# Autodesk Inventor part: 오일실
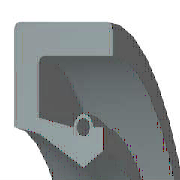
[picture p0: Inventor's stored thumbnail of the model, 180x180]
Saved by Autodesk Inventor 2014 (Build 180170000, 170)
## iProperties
IsCustomPart: 0
Created: 2016-05
Part Number: 오일실
Material: 고무
Description: 오일-실
Document SubType Name: Modeling
Standard: KS B 2804
Designer: mduedu
Standards Organization: KS
Language: ko-KR
Size Designation: S - 17 30 8
Categories: <MemberInstance><Categories><Category DisplayName="샤프트 부품" InternalName="7f7aeb1f-a693-4053-b835-cee3144e0d98" Mnemonic="SHFT"><Category DisplayName="실링" Intern
Density: 0.93 g/cm^3
Appearance: 고무 - 검은색 - 버전 1.1
Author: mduedu
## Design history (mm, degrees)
revolve "본체" stored, may be unused: angle "d17" = 90 deg
revolve "스프링1" stored, may be unused: angle "d18" = 90 deg
body "Solid1"
sketch "스케치1"
  geometry: L1 (0, 15)-(8, 15); L2 (8, 15)-(8, 13.75); L3 (8, 13.75)-(1.75, 13.75); L4 (0, 15)-(0, 10.6); L5 (0, 10.6)-(1.75, 10.25); L6 (1.75, 10.25)-(4.9, 8.5); L7 (4.9, 8.5)-(0, 8.5); L8 (6.3, 9.375)-(6.3, 10.6); L9 (0, 0)-(9.586, 0) reference; L10 (4.9, 8.5)-(6.3, 9.375); L11 (0, 18)-(0, -3) reference; L12 (-1.917, 0)-(11.503, 0) reference; L13 (4.2, 10.6)-(1.75, 11.09); L14 (1.75, 11.09)-(1.75, 13.75); L15 (6.3, 10.6)-(5.6, 10.6); C1 r 0.455 at (4.9, 10.6); A1 r 0.7 centre (4.9, 10.6) between (5.6, 10.6) and (4.2, 10.6)
  constraints: 26 end point, 5 horizontal alignment, 4 perpendicular, 2 centre point, 2 collinear, 2 horizontal, 2 parallel, 2 point on circle, 2 point on line, 2 vertical alignment, 1 coincident
  dimensions: "d0" = 30 diameter of L1 L9 (= SD2); "d1" = 18.75 diameter of L8.start L9 (= ABDM); "d2" = 1.25 distance of L1.end L2.end (computed from SD); "d3" = 0.91 diameter of C1 (= SPDI); "d4" = 1.4 diameter of A1 (= SPDA); "d5" = 17 diameter of L6.end L9 (= NND); "d6" = 20.5 diameter of L5.end L9 (= TKDM); "d7" = 21.2 diameter of L4.end L9 (= HLDM); "d8" = 4.9 distance from line of C1.centre L4 (= SPDST); "d9" = 6.3 distance between parallel lines of L8 L4 (= SDI); "d10" = 8 distance between parallel lines of L2 L4 (= SWDT); "d12" = 1.75 distance between parallel lines of L14 L4 (= SD)
fillet "모깎기1" dims "d11" = 0.3 (= RR)
other parameters: "SD2" = 30 [user parameter; used in 1 equation term], "SWDT" = 8 [user parameter; used in 1 equation term], "RR" = 0.3 [user parameter; used in 1 equation term], "SD" = 1.75 [user parameter; used in 2 equation terms], "NND" = 17 [user parameter; used in 1 equation term], "SPDA" = 1.4 [user parameter; used in 1 equation term], "SPDI" = 0.91 [user parameter; used in 1 equation term], "TKDM" = 20.5 [user parameter; used in 1 equation term], "HLDM" = 21.2 [user parameter; used in 1 equation term], "ABDM" = 18.75 [user parameter; used in 1 equation term], "SDI" = 6.3 [user parameter; used in 1 equation term], "SPDST" = 4.9 [user parameter; used in 1 equation term], "d13" = 0, "d14" = 0, "d15" = 0, "LAB" = 0.35 [user parameter]
